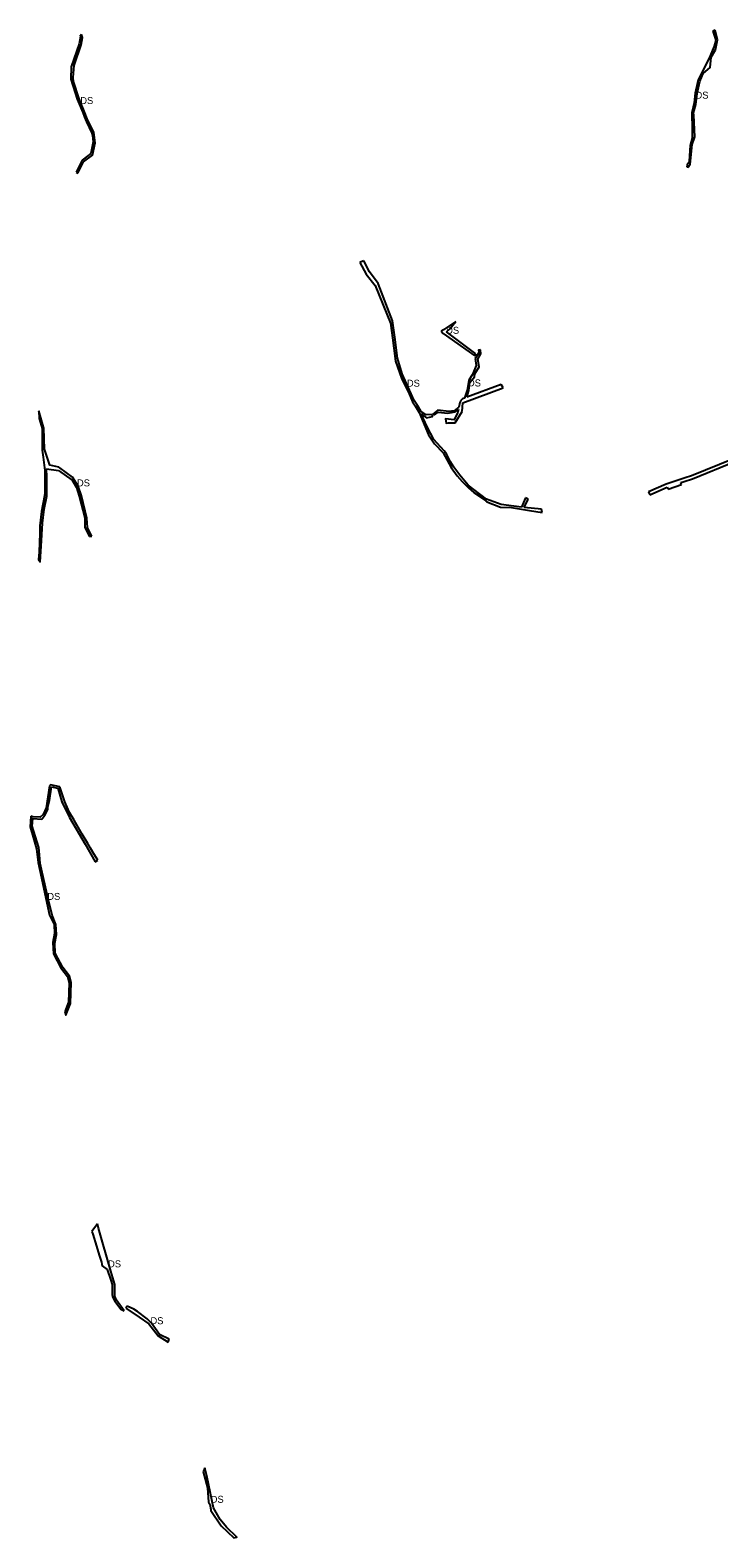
# Model space of a CAD drawing. Extents: x -477304 to -465641, y -1159113 to -1149285.
# Drawn here: x -476564 to -475675, y -1153650 to -1151706 of the extents above; entities that cross this region are included whole.
import ezdxf

# ---------------------------------------------------------------- set-up
doc = ezdxf.new("R2010")
doc.units = 0
doc.layers.add('35', color=7, linetype='Continuous')

msp = doc.modelspace()

# ---------------------------------------------------------------- linework, layer by layer
at = {"layer": '35'}
for p, q in [((-476496.4, -1151712.6), (-476499, -1151711.6)), ((-475679.8, -1151705.7), (-475682.7, -1151707.2)), ((-475682.7, -1151707.2), (-475679, -1151718.8)), ((-476500.2, -1151723.2), (-476510.5, -1151753.2)), ((-476506.8, -1151751.5), (-476497.7, -1151724.6)), ((-476497.7, -1151724.6), (-476495.9, -1151715.3)), ((-476495.9, -1151715.3), (-476496.4, -1151712.6)), ((-476510.5, -1151753.2), (-476511.1, -1151769.1)), ((-476507.9, -1151766.6), (-476506.8, -1151751.5)), ((-476507.8, -1151772), (-476507.9, -1151766.6)), ((-476500.2, -1151794.2), (-476507.8, -1151772)), ((-476493.1, -1151812.3), (-476500.2, -1151794.2)), ((-476493.5, -1151817.9), (-476491, -1151824.1)), ((-476490.1, -1151820), (-476493.1, -1151812.3)), ((-476491, -1151824.1), (-476483.8, -1151838.4)), ((-476489.3, -1151822), (-476490.1, -1151820)), ((-476481.4, -1151837.2), (-476489.3, -1151822)), ((-475709.8, -1151812.2), (-475709.6, -1151833.6)), ((-475706.1, -1151843.4), (-475707.5, -1151815.4)), ((-476481, -1151840.7), (-476481.4, -1151837.2)), ((-476479.7, -1151851.1), (-476481, -1151840.7)), ((-475709.4, -1151853.3), (-475706.1, -1151843.4)), ((-476496.5, -1151873.5), (-476504.3, -1151888.7)), ((-476502.2, -1151890.3), (-476494.6, -1151875.4)), ((-475716.2, -1151881.8), (-475714.8, -1151882.6)), ((-476504.3, -1151888.7), (-476502.2, -1151890.3)), ((-476133.6, -1152003.2), (-476138, -1152005.6)), ((-476138, -1152005.6), (-476129.9, -1152020.3)), ((-476129.9, -1152020.3), (-476118.4, -1152035.2)), ((-476114.4, -1152032.6), (-476125.6, -1152017.3)), ((-476014.5, -1152081.6), (-476030.4, -1152092.2)), ((-476030.4, -1152092.2), (-476033.2, -1152094.1)), ((-476033.2, -1152094.1), (-476030.7, -1152096.8)), ((-476030.7, -1152096.8), (-475989.8, -1152125.9)), ((-475988.7, -1152123.1), (-476026.5, -1152095)), ((-476096.1, -1152102.4), (-476092.3, -1152132.7)), ((-476092.3, -1152132.7), (-476084.3, -1152154.4)), ((-475989.8, -1152125.9), (-475988.7, -1152123.1)), ((-475984.4, -1152121.2), (-475989.2, -1152129.1)), ((-476084.3, -1152154.4), (-476074.7, -1152174.7)), ((-476074.7, -1152174.7), (-476070.2, -1152185.3)), ((-476005.2, -1152186.4), (-475953.4, -1152167.1)), ((-475999.7, -1152169.9), (-476003, -1152180.2)), ((-475956, -1152162.9), (-476000.1, -1152179.2)), ((-476000.1, -1152179.2), (-475997.6, -1152170.4)), ((-475953.4, -1152167.1), (-475956, -1152162.9)), ((-476547, -1152214.8), (-476552.3, -1152196.8)), ((-476552.3, -1152196.8), (-476551.9, -1152206.7)), ((-476070.2, -1152185.3), (-476067, -1152190.4)), ((-476064, -1152190), (-476067.9, -1152183.3)), ((-476067, -1152190.4), (-476061.8, -1152198.7)), ((-476037.5, -1152195.8), (-476044, -1152201.2)), ((-476041.9, -1152201.9), (-476037.1, -1152198.4)), ((-476023.5, -1152197.5), (-476037.5, -1152195.8)), ((-476015.2, -1152212.2), (-476006.2, -1152197.5)), ((-476015.1, -1152198), (-476011.1, -1152194.9)), ((-476005.9, -1152181.3), (-476007.7, -1152183.3)), ((-476006.2, -1152197.5), (-476005.2, -1152186.4)), ((-476003, -1152180.2), (-476005.9, -1152181.3)), ((-476551.9, -1152206.7), (-476548.2, -1152219.6)), ((-476051.2, -1152217.4), (-476058.9, -1152200.8)), ((-476058.9, -1152200.8), (-476052, -1152205.7)), ((-476044, -1152201.2), (-476041.9, -1152201.9)), ((-476024.2, -1152212.4), (-476020.7, -1152212.4)), ((-476020.7, -1152212.4), (-476015.2, -1152212.2)), ((-476546.8, -1152256.5), (-476544.8, -1152273.7)), ((-476041.8, -1152239.4), (-476030.8, -1152250.9)), ((-476030.8, -1152250.9), (-476020.3, -1152269.8)), ((-476021.2, -1152262.7), (-476026.5, -1152252.4)), ((-476544.8, -1152273.7), (-476544.8, -1152285.7)), ((-476542.1, -1152282.5), (-476542.6, -1152271.4)), ((-476542.6, -1152271.4), (-476527.1, -1152273.6)), ((-476527.1, -1152273.6), (-476509.4, -1152286.3)), ((-476525.4, -1152270.2), (-476526.7, -1152269.5)), ((-476508.8, -1152282.4), (-476525.4, -1152270.2)), ((-476020.3, -1152269.8), (-476012.5, -1152280.8)), ((-476544.8, -1152285.7), (-476544.6, -1152302.3)), ((-476542.2, -1152296.7), (-476542.1, -1152286.5)), ((-476542.1, -1152286.5), (-476542.1, -1152282.5)), ((-476509.4, -1152286.3), (-476503.9, -1152295.6)), ((-476503.9, -1152295.6), (-476500.2, -1152306.7)), ((-475742.9, -1152291.4), (-475765.6, -1152301.2)), ((-475764, -1152304.9), (-475741.5, -1152295.2)), ((-475718.5, -1152283.3), (-475742.9, -1152291.4)), ((-475741.5, -1152295.2), (-475740.6, -1152297.6)), ((-475740.6, -1152297.6), (-475723.3, -1152291.6)), ((-475724.1, -1152289.4), (-475719.6, -1152287.9)), ((-475723.3, -1152291.6), (-475724.1, -1152289.4)), ((-476542, -1152306.8), (-476542.2, -1152296.7)), ((-475975.5, -1152313.4), (-475974.2, -1152314.2)), ((-475955.9, -1152317.7), (-475974.6, -1152310.7)), ((-475974.2, -1152314.2), (-475956.7, -1152320.8)), ((-475924.6, -1152309), (-475929.7, -1152321)), ((-475926.2, -1152321.5), (-475921.1, -1152310.9)), ((-475921.1, -1152310.9), (-475924.6, -1152309)), ((-475765.6, -1152301.2), (-475764, -1152304.9)), ((-475956.7, -1152320.8), (-475942.6, -1152321.5)), ((-475929.7, -1152321), (-475955.9, -1152317.7)), ((-475942.6, -1152321.5), (-475919.3, -1152325.3)), ((-475904, -1152323.4), (-475926.2, -1152321.5)), ((-475919.3, -1152325.3), (-475903.1, -1152328)), ((-475903.1, -1152328), (-475904, -1152323.4)), ((-476549.5, -1152371.5), (-476547.5, -1152341.7)), ((-476492.8, -1152347.1), (-476486.9, -1152359)), ((-476484.1, -1152358.5), (-476489.6, -1152347.3)), ((-476486.9, -1152359), (-476484.1, -1152358.5)), ((-476538.7, -1152680.3), (-476542.7, -1152709)), ((-476538.6, -1152699.2), (-476536, -1152681.8)), ((-476536, -1152681.8), (-476527.8, -1152683.3)), ((-476527.8, -1152683.3), (-476522.6, -1152701.2)), ((-476540.6, -1152707.8), (-476538.6, -1152699.2)), ((-476562.5, -1152719.5), (-476563.6, -1152733.4)), ((-476560, -1152720.4), (-476562.5, -1152719.5)), ((-476540.7, -1152711), (-476540.6, -1152707.8)), ((-476506.9, -1152724.7), (-476512.8, -1152714.7)), ((-476563.6, -1152733.4), (-476558.7, -1152749.8)), ((-476496.3, -1152742.8), (-476506.9, -1152724.7)), ((-476551.3, -1152769.3), (-476552.4, -1152760.1)), ((-476492.6, -1152755.9), (-476479.5, -1152778.5)), ((-476481.3, -1152768.3), (-476485.8, -1152760.9)), ((-476476.4, -1152776.5), (-476481.3, -1152768.3)), ((-476479.5, -1152778.5), (-476476.4, -1152776.5)), ((-476551.2, -1152789.4), (-476538.4, -1152847.1)), ((-476540.4, -1152826.3), (-476548.9, -1152788.5)), ((-476535.2, -1152847.3), (-476540.4, -1152826.3)), ((-476538.4, -1152847.1), (-476532.5, -1152859.2)), ((-476533.5, -1152897.1), (-476524, -1152915.1)), ((-476476.8, -1153245.6), (-476484, -1153255.4)), ((-476484, -1153255.4), (-476482.9, -1153258.9)), ((-476482.9, -1153258.9), (-476477.9, -1153274.4)), ((-476477.9, -1153274.4), (-476474.3, -1153285.9)), ((-476474.3, -1153285.9), (-476471.4, -1153294.9)), ((-476471.4, -1153294.9), (-476470.9, -1153297.4)), ((-476464.1, -1153304.5), (-476459.6, -1153318.1)), ((-476459.6, -1153318.1), (-476457.6, -1153323.6)), ((-476454.2, -1153323.6), (-476456.8, -1153315.1)), ((-476454.4, -1153345.2), (-476446.6, -1153355.6)), ((-476442.1, -1153357.5), (-476452, -1153343.9)), ((-476446.6, -1153355.6), (-476442.1, -1153357.5)), ((-476438.6, -1153351.8), (-476440.1, -1153354.3)), ((-476429.6, -1153355.3), (-476438.6, -1153351.8)), ((-476424.9, -1153358.7), (-476429.6, -1153355.3)), ((-476396.6, -1153388.2), (-476407.2, -1153373.7)), ((-476384.2, -1153394.2), (-476396.6, -1153388.2)), ((-476385.4, -1153398), (-476384.2, -1153394.2)), ((-476338.2, -1153560.2), (-476340.5, -1153565.5)), ((-476340.5, -1153565.5), (-476334.7, -1153585.8)), ((-476335.5, -1153570.4), (-476338.2, -1153560.2)), ((-476327.1, -1153611.8), (-476335.5, -1153570.4)), ((-476334.7, -1153585.8), (-476333.3, -1153604.4)), ((-476333.3, -1153604.4), (-476331.8, -1153607)), ((-476318.6, -1153626.7), (-476327.1, -1153611.8)), ((-476310.3, -1153636.7), (-476318.6, -1153626.7))]:
    msp.add_line(p, q, dxfattribs=at)
for points in [[(-476499, -1151711.6), (-476498.5, -1151714.1), (-476500.2, -1151723.2)], [(-475699.7, -1151772.1), (-475695.4, -1151761.8), (-475686.4, -1151753.9), (-475684.8, -1151740.7), (-475679.4, -1151731), (-475676.6, -1151718.2), (-475679.8, -1151705.7)], [(-475679, -1151718.8), (-475681, -1151726.3), (-475687.4, -1151741.9)], [(-475687.4, -1151741.9), (-475701.6, -1151769.9), (-475705.4, -1151787.2), (-475706.7, -1151799.6), (-475709.8, -1151812.2)], [(-476511.1, -1151769.1), (-476502.9, -1151794.6), (-476495.8, -1151811.9), (-476493.5, -1151817.9)], [(-475704.9, -1151801.4), (-475703.2, -1151787.4), (-475699.7, -1151772.1)], [(-475707.5, -1151815.4), (-475707.8, -1151812.2), (-475704.9, -1151801.4)], [(-476483.8, -1151838.4), (-476483.3, -1151841.4), (-476482.1, -1151849.8)], [(-475709.6, -1151833.6), (-475709.5, -1151845.2), (-475712.1, -1151854.3)], [(-476482.1, -1151849.8), (-476485.2, -1151865), (-476496.5, -1151873.5)], [(-476494.6, -1151875.4), (-476483, -1151867), (-476479.7, -1151851.1)], [(-475712.1, -1151854.3), (-475713.5, -1151874.6), (-475712.8, -1151875.3), (-475715.7, -1151879.3), (-475716.2, -1151881.8)], [(-475714.8, -1151882.6), (-475712.2, -1151878.5), (-475709.4, -1151853.3)], [(-476125.6, -1152017.3), (-476132.2, -1152005), (-476133.6, -1152003.2)], [(-476118.4, -1152035.2), (-476098.5, -1152083.5), (-476096.1, -1152102.4)], [(-476093.2, -1152101.6), (-476095.9, -1152080.8), (-476114.4, -1152032.6)], [(-476026.5, -1152095), (-476022.1, -1152090.9), (-476014.5, -1152081.6)], [(-476067.9, -1152183.3), (-476083.4, -1152149), (-476089.8, -1152128.9), (-476093.2, -1152101.6)], [(-475997.6, -1152170.4), (-475996.3, -1152160.2), (-475990.4, -1152152.9), (-475989.7, -1152149.1), (-475984.4, -1152140.2), (-475986, -1152130.2), (-475981.9, -1152123.2), (-475982.5, -1152118.1)], [(-475982.5, -1152118.1), (-475985.3, -1152118.3), (-475984.4, -1152121.2)], [(-475989.2, -1152129.1), (-475988, -1152138.3), (-475992.8, -1152150)], [(-475992.8, -1152150), (-475997.7, -1152157), (-475999.7, -1152169.9)], [(-476045, -1152201.3), (-476052.6, -1152202.1), (-476059.7, -1152197.3), (-476064, -1152190)], [(-476037.1, -1152198.4), (-476024.7, -1152199.7), (-476015.1, -1152198)], [(-476011.1, -1152194.9), (-476011.8, -1152198.4), (-476016.7, -1152208.2), (-476027.9, -1152207.1), (-476026.9, -1152212.5), (-476024.2, -1152212.4)], [(-476010.5, -1152192.2), (-476016.6, -1152196.9), (-476023.5, -1152197.5)], [(-476007.7, -1152183.3), (-476009.2, -1152185.8), (-476010.5, -1152192.2)], [(-476545.2, -1152246.4), (-476545.7, -1152219), (-476547, -1152214.8)], [(-476061.8, -1152198.7), (-476049.5, -1152227.6), (-476041.8, -1152239.4)], [(-476052, -1152205.7), (-476044.6, -1152204.2), (-476045, -1152201.3)], [(-476026.5, -1152252.4), (-476029.4, -1152248.4), (-476042.8, -1152233.6), (-476051.2, -1152217.4)], [(-476548.2, -1152219.6), (-476547.9, -1152247.4), (-476546.8, -1152256.5)], [(-476526.7, -1152269.5), (-476538.1, -1152266.8), (-476545.2, -1152246.4)], [(-475652.6, -1152256.2), (-475656.3, -1152258.7), (-475710.5, -1152280.6), (-475718.5, -1152283.3)], [(-476009.1, -1152279.7), (-476017, -1152269.5), (-476021.2, -1152262.7)], [(-475719.6, -1152287.9), (-475709.1, -1152284.4), (-475654.4, -1152262.3), (-475650.3, -1152259.5)], [(-476497.4, -1152306.4), (-476501.5, -1152294), (-476508.8, -1152282.4)], [(-476012.5, -1152280.8), (-476006, -1152288.1), (-475997.8, -1152296.1), (-475991, -1152302)], [(-475974.6, -1152310.7), (-475998.3, -1152292.5), (-476009.1, -1152279.7)], [(-476544.6, -1152302.3), (-476544.9, -1152306.4), (-476549, -1152326.4)], [(-476547.5, -1152341.7), (-476545.4, -1152323.4), (-476542, -1152306.8)], [(-476500.2, -1152306.7), (-476493.1, -1152334.6), (-476492.8, -1152347.1)], [(-476489.6, -1152347.3), (-476490.4, -1152335.1), (-476497.4, -1152306.4)], [(-475991, -1152302), (-475976.1, -1152312.1), (-475975.5, -1152313.4)], [(-476549, -1152326.4), (-476551, -1152344.9), (-476551.2, -1152354.5)], [(-476551.2, -1152354.5), (-476551.9, -1152379.2), (-476552.8, -1152388.5), (-476550.8, -1152391.6), (-476549.5, -1152371.5)], [(-476525.1, -1152681.9), (-476537.4, -1152679), (-476538.7, -1152680.3)], [(-476512.8, -1152714.7), (-476519, -1152701), (-476525.1, -1152681.9)], [(-476522.6, -1152701.2), (-476512.6, -1152721.2), (-476492.6, -1152755.9)], [(-476552.4, -1152760.1), (-476561.1, -1152732.4), (-476560.3, -1152722.7), (-476548.6, -1152723.3)], [(-476542.7, -1152709), (-476546.8, -1152717.5), (-476550.7, -1152721), (-476560, -1152720.4)], [(-476548.6, -1152723.3), (-476544.6, -1152718.4), (-476540.7, -1152711)], [(-476485.8, -1152760.9), (-476489.3, -1152754.9), (-476496.3, -1152742.8)], [(-476558.7, -1152749.8), (-476555.2, -1152761.9), (-476553.3, -1152779.5), (-476551.2, -1152789.4)], [(-476548.9, -1152788.5), (-476550.7, -1152780.7), (-476551.3, -1152769.3)], [(-476531.6, -1152883.4), (-476529.6, -1152872.3), (-476530.5, -1152859.2), (-476535.2, -1152847.3)], [(-476532.5, -1152859.2), (-476532, -1152871.1), (-476534.2, -1152882.5), (-476533.5, -1152897.1)], [(-476521.4, -1152914.9), (-476531.1, -1152896.1), (-476531.6, -1152883.4)], [(-476524, -1152915.1), (-476515.4, -1152926.2), (-476513.1, -1152934.4)], [(-476518.9, -1152972.1), (-476517.5, -1152976.2), (-476513.2, -1152965.6), (-476511.4, -1152961.1), (-476510.7, -1152934.2), (-476512.7, -1152926.1), (-476521.4, -1152914.9)], [(-476513.1, -1152934.4), (-476514, -1152959.5), (-476518.9, -1152972.1)], [(-476456.8, -1153315.1), (-476459.3, -1153306.5), (-476475.4, -1153251), (-476476.8, -1153245.6)], [(-476470.9, -1153297.4), (-476470.5, -1153299.6), (-476464.1, -1153304.5)], [(-476457.6, -1153323.6), (-476457.8, -1153336.4), (-476457.3, -1153339.7), (-476454.4, -1153345.2)], [(-476452, -1153343.9), (-476454.2, -1153338.9), (-476454.2, -1153323.6)], [(-476440.1, -1153354.3), (-476422.8, -1153366), (-476410.6, -1153374.4), (-476398.6, -1153389.9), (-476385.4, -1153398)], [(-476407.2, -1153373.7), (-476412.4, -1153368), (-476424.9, -1153358.7)], [(-476331.8, -1153607), (-476330.3, -1153614.1), (-476330.4, -1153615.2), (-476317, -1153634.8), (-476300.7, -1153650.5), (-476297.1, -1153649.7), (-476310.3, -1153636.7)]]:
    msp.add_lwpolyline(points, dxfattribs=at)

# ---------------------------------------------------------------- texts
for p in [(-475705.1, -1151794.1), (-476498.9, -1151801), (-476026.8, -1152097.4), (-476077.5, -1152165.6), (-475998.7, -1152165.3), (-476503.1, -1152294.2), (-476541.4, -1152827.6), (-476463, -1153301.6), (-476408.3, -1153374.9), (-476330.6, -1153605.3)]:
    msp.add_text('DS', height=9, dxfattribs=at).set_placement(p)

doc.saveas('drawing.dxf')
